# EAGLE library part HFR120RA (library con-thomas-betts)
THOMAS&BETTS
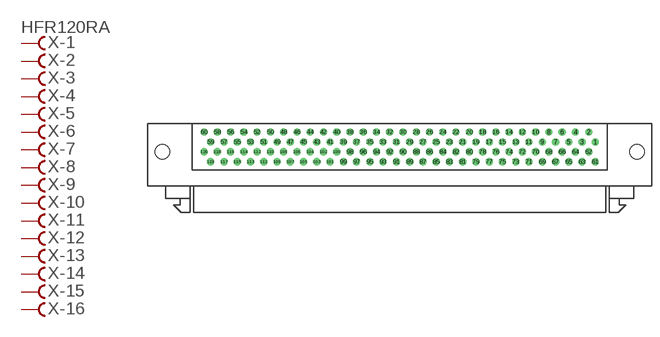
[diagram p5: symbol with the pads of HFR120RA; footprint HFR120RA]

Designator prefix X; gates -1=FV -2=F -3=F -4=F -5=F -6=F -7=F -8=F -9=F -10=F -11=F -12=F -13=F -14=F -15=F -16=F -17=F -18=F -19=F -20=F -21=F -22=F -23=F -24=F -25=F -26=F -27=F -28=F -29=F -30=F -32=F -33=F -34=F -35=F -36=F -37=F -38=F -39=F -40=F -41=F -42=F -43=F -44=F -45=F -46=F -47=F -48=F -49=F -50=F -51=F -52=F -53=F -54=F -55=F -56=F -57=F -58=F -59=F -60=F -62=F -63=F -64=F -65=F -66=F -67=F -68=F -69=F -70=F -71=F -72=F -73=F -74=F -75=F -76=F -77=F -78=F -79=F -80=F -81=F -82=F -83=F -84=F -85=F -86=F -87=F -88=F -89=F -90=F -92=F -93=F -94=F -95=F -96=F -97=F -98=F -99=F -100=F -101=F -102=F -103=F -104=F -105=F -106=F -107=F -108=F -109=F -110=F -111=F -112=F -113=F -114=F -115=F -116=F -117=F -118=F -119=F -120=F -31=F -61=F -91=F

## HFR120RA  [HFR120RA]
1  -1:F  pas
2  -2:F  pas
3  -3:F  pas
4  -4:F  pas
5  -5:F  pas
6  -6:F  pas
7  -7:F  pas
8  -8:F  pas
9  -9:F  pas
10  -10:F  pas
11  -11:F  pas
12  -12:F  pas
13  -13:F  pas
14  -14:F  pas
15  -15:F  pas
16  -16:F  pas
17  -17:F  pas
18  -18:F  pas
19  -19:F  pas
20  -20:F  pas
21  -21:F  pas
22  -22:F  pas
23  -23:F  pas
24  -24:F  pas
25  -25:F  pas
26  -26:F  pas
27  -27:F  pas
28  -28:F  pas
29  -29:F  pas
30  -30:F  pas
31  -31:F  pas
32  -32:F  pas
33  -33:F  pas
34  -34:F  pas
35  -35:F  pas
36  -36:F  pas
37  -37:F  pas
38  -38:F  pas
39  -39:F  pas
40  -40:F  pas
41  -41:F  pas
42  -42:F  pas
43  -43:F  pas
44  -44:F  pas
45  -45:F  pas
46  -46:F  pas
47  -47:F  pas
48  -48:F  pas
49  -49:F  pas
50  -50:F  pas
51  -51:F  pas
52  -52:F  pas
53  -53:F  pas
54  -54:F  pas
55  -55:F  pas
56  -56:F  pas
57  -57:F  pas
58  -58:F  pas
59  -59:F  pas
60  -60:F  pas
61  -61:F  pas
62  -62:F  pas
63  -63:F  pas
64  -64:F  pas
65  -65:F  pas
66  -66:F  pas
67  -67:F  pas
68  -68:F  pas
69  -69:F  pas
70  -70:F  pas
71  -71:F  pas
72  -72:F  pas
73  -73:F  pas
74  -74:F  pas
75  -75:F  pas
76  -76:F  pas
77  -77:F  pas
78  -78:F  pas
79  -79:F  pas
80  -80:F  pas
81  -81:F  pas
82  -82:F  pas
83  -83:F  pas
84  -84:F  pas
85  -85:F  pas
86  -86:F  pas
87  -87:F  pas
88  -88:F  pas
89  -89:F  pas
90  -90:F  pas
91  -91:F  pas
92  -92:F  pas
93  -93:F  pas
94  -94:F  pas
95  -95:F  pas
96  -96:F  pas
97  -97:F  pas
98  -98:F  pas
99  -99:F  pas
100  -100:F  pas
101  -101:F  pas
102  -102:F  pas
103  -103:F  pas
104  -104:F  pas
105  -105:F  pas
106  -106:F  pas
107  -107:F  pas
108  -108:F  pas
109  -109:F  pas
110  -110:F  pas
111  -111:F  pas
112  -112:F  pas
113  -113:F  pas
114  -114:F  pas
115  -115:F  pas
116  -116:F  pas
117  -117:F  pas
118  -118:F  pas
119  -119:F  pas
120  -120:F  pas

## Footprint HFR120RA (pad centres in mm)
THOMAS&BETTS
drill 0.864 octagon: 1 37.465,6.985
drill 0.864 round: 2 36.195,8.89; 3 34.925,6.985; 4 33.655,8.89; 5 32.385,6.985; 6 31.115,8.89; 7 29.845,6.985; 8 28.575,8.89; 9 27.305,6.985; 10 26.035,8.89; 11 24.765,6.985; 12 23.495,8.89; 13 22.225,6.985; 14 20.955,8.89; 15 19.685,6.985; 16 18.415,8.89; 17 17.145,6.985; 18 15.875,8.89; 19 14.605,6.985; 20 13.335,8.89; 21 12.065,6.985; 22 10.795,8.89; 23 9.525,6.985; 24 8.255,8.89; 25 6.985,6.985; 26 5.715,8.89; 27 4.445,6.985; 28 3.175,8.89; 29 1.905,6.985; 30 0.635,8.89; 31 -0.635,6.985; 32 -1.905,8.89; 33 -3.175,6.985; 34 -4.445,8.89; 35 -5.715,6.985; 36 -6.985,8.89; 37 -8.255,6.985; 38 -9.525,8.89; 39 -10.795,6.985; 40 -12.065,8.89; 41 -13.335,6.985; 42 -14.605,8.89; 43 -15.875,6.985; 44 -17.145,8.89; 45 -18.415,6.985; 46 -19.685,8.89; 47 -20.955,6.985; 48 -22.225,8.89; 49 -23.495,6.985; 50 -24.765,8.89; 51 -26.035,6.985; 52 -27.305,8.89; 53 -28.575,6.985; 54 -29.845,8.89; 55 -31.115,6.985; 56 -32.385,8.89; 57 -33.655,6.985; 58 -34.925,8.89; 59 -36.195,6.985; 60 -37.465,8.89; 61 37.465,3.175; 62 36.195,5.08; 63 34.925,3.175; 64 33.655,5.08; 65 32.385,3.175; 66 31.115,5.08; 67 29.845,3.175; 68 28.575,5.08; 69 27.305,3.175; 70 26.035,5.08; 71 24.765,3.175; 72 23.495,5.08; 73 22.225,3.175; 74 20.955,5.08; 75 19.685,3.175; 76 18.415,5.08; 77 17.145,3.175; 78 15.875,5.08; 79 14.605,3.175; 80 13.335,5.08; 81 12.065,3.175; 82 10.795,5.08; 83 9.525,3.175; 84 8.255,5.08; 85 6.985,3.175; 86 5.715,5.08; 87 4.445,3.175; 88 3.175,5.08; 89 1.905,3.175; 90 0.635,5.08; 91 -0.635,3.175; 92 -1.905,5.08; 93 -3.175,3.175; 94 -4.445,5.08; 95 -5.715,3.175; 96 -6.985,5.08; 97 -8.255,3.175; 98 -9.525,5.08; 99 -10.795,3.175; 100 -12.065,5.08; 101 -13.335,3.175; 102 -14.605,5.08; 103 -15.875,3.175; 104 -17.145,5.08; 105 -18.415,3.175; 106 -19.685,5.08; 107 -20.955,3.175; 108 -22.225,5.08; 109 -23.495,3.175; 110 -24.765,5.08; 111 -26.035,3.175; 112 -27.305,5.08; 113 -28.575,3.175; 114 -29.845,5.08; 115 -31.115,3.175; 116 -32.385,5.08; 117 -33.655,3.175; 118 -34.925,5.08; 119 -36.195,3.175; 120 -37.465,5.08
hole 2.769 at 45.466,5.08
hole 2.769 at -45.466,5.08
